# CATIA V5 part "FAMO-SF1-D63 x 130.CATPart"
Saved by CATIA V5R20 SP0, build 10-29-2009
Part number: FAMO-SF1-D63 x 130
Definition: NONE
Nomenclature: FAMO-SF1-D63 x 130
Source: Unknown
Description: FAMO-SF1-D63 x 130
Bounding box of the stored display mesh (mm): x -63 to 67, y -46 to 46, z -46 to 46
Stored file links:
  C:\Users\Utente\Desktop\IO LAVORO\3D X SITO CF\X SITO\FAMO\FAMO-SF1-D63 x 130.CATPart

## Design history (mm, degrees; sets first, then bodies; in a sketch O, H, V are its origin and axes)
Body1 "FAMO-SF1-D63 x 130" (main body)
  Solid1: solid without history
